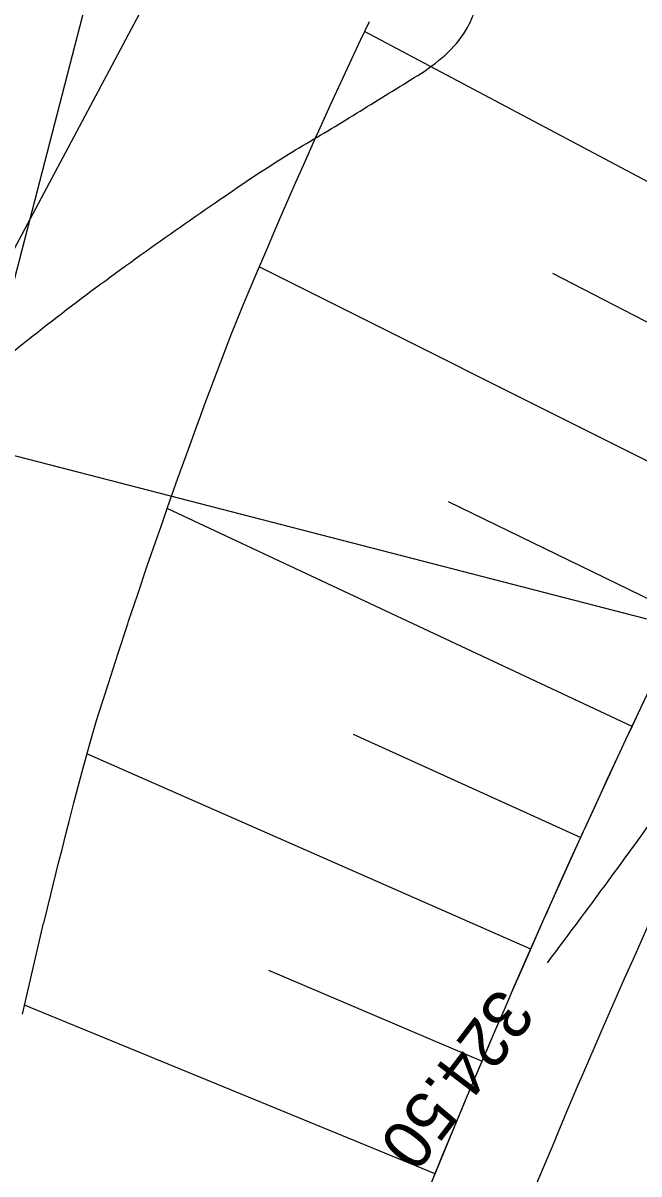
# Model space of a CAD drawing. Extents: x -564043 to -563833, y -1163561 to -1163412.
# Drawn here: x -563977.47 to -563971.17, y -1163485.61 to -1163473.83 of the extents above; entities that cross this region are included whole.
import ezdxf

# ---------------------------------------------------------------- set-up
doc = ezdxf.new("R2010")
doc.units = 0
for name, color, linetype in [('5', 7, 'Continuous'), ('_popis staničení T1', 7, 'Continuous'), ('Definiční bod kú', 7, 'Continuous'), ('Line', 7, 'Continuous'), ('Vrstva 24', 7, 'Continuous'), ('Vrstva 25', 7, 'Continuous'), ('Vrstva 26', 7, 'Continuous')]:
    doc.layers.add(name, color=color, linetype=linetype)

msp = doc.modelspace()

# ---------------------------------------------------------------- linework, layer by layer
for points in [[(-563973.328, -1163485.785), (-563972.941, -1163484.852), (-563972.655, -1163484.178), (-563972.545, -1163483.923), (-563972.444, -1163483.689), (-563972.14, -1163482.998), (-563971.736, -1163482.1), (-563971.725, -1163482.077), (-563971.302, -1163481.16), (-563970.869, -1163480.247), (-563970.771, -1163480.044), (-563970.427, -1163479.339), (-563969.976, -1163478.435), (-563969.759, -1163478.009), (-563969.516, -1163477.536), (-563969.047, -1163476.642), (-563968.703, -1163475.998), (-563968.571, -1163475.754), (-563968.096, -1163474.874), (-563967.621, -1163473.994), (-563967.145, -1163473.115)], [(-563977.473, -1163483.969), (-563977.402, -1163483.659), (-563977.329, -1163483.35), (-563977.256, -1163483.041), (-563977.255, -1163483.039), (-563977.18, -1163482.732), (-563977.103, -1163482.424), (-563977.068, -1163482.285), (-563977.025, -1163482.116), (-563976.995, -1163482), (-563976.946, -1163481.808), (-563976.865, -1163481.5), (-563976.782, -1163481.193), (-563976.715, -1163480.966), (-563976.691, -1163480.89), (-563976.594, -1163480.588), (-563976.497, -1163480.287), (-563976.398, -1163479.986), (-563976.395, -1163479.977), (-563976.387, -1163479.951), (-563976.298, -1163479.685), (-563976.196, -1163479.385), (-563976.093, -1163479.085), (-563976.042, -1163478.94), (-563975.988, -1163478.786), (-563975.883, -1163478.488), (-563975.775, -1163478.189), (-563975.682, -1163477.935), (-563975.667, -1163477.891), (-563975.6, -1163477.71), (-563975.556, -1163477.594), (-563975.445, -1163477.297), (-563975.332, -1163477.001), (-563975.305, -1163476.935), (-563975.211, -1163476.708), (-563975.089, -1163476.416), (-563974.965, -1163476.124), (-563974.891, -1163475.952), (-563974.84, -1163475.833), (-563974.714, -1163475.543), (-563974.69, -1163475.488), (-563974.586, -1163475.253), (-563974.462, -1163474.975), (-563974.457, -1163474.964), (-563974.326, -1163474.675), (-563974.194, -1163474.388), (-563974.06, -1163474.1), (-563974.016, -1163474.005), (-563973.925, -1163473.814)], [(-563977.473, -1163483.969), (-563977.402, -1163483.659), (-563977.329, -1163483.35), (-563977.256, -1163483.041), (-563977.255, -1163483.039), (-563977.18, -1163482.732), (-563977.103, -1163482.424), (-563977.068, -1163482.285), (-563977.025, -1163482.116), (-563976.995, -1163482), (-563976.946, -1163481.808), (-563976.865, -1163481.5), (-563976.782, -1163481.193), (-563976.715, -1163480.966), (-563976.691, -1163480.89), (-563976.594, -1163480.588), (-563976.497, -1163480.287), (-563976.398, -1163479.986), (-563976.395, -1163479.977), (-563976.387, -1163479.951), (-563976.298, -1163479.685), (-563976.196, -1163479.385), (-563976.093, -1163479.085), (-563976.042, -1163478.94), (-563975.988, -1163478.786), (-563975.883, -1163478.488), (-563975.775, -1163478.189), (-563975.682, -1163477.935), (-563975.667, -1163477.891), (-563975.6, -1163477.71), (-563975.556, -1163477.594), (-563975.445, -1163477.297), (-563975.332, -1163477.001), (-563975.305, -1163476.935), (-563975.211, -1163476.708), (-563975.089, -1163476.416), (-563974.965, -1163476.124), (-563974.891, -1163475.952), (-563974.84, -1163475.833), (-563974.714, -1163475.543), (-563974.69, -1163475.488), (-563974.586, -1163475.253), (-563974.462, -1163474.975), (-563974.457, -1163474.964), (-563974.326, -1163474.675), (-563974.194, -1163474.388), (-563974.06, -1163474.1), (-563974.016, -1163474.005), (-563973.925, -1163473.814)], [(-563973.287, -1163485.685), (-563973.173, -1163485.407), (-563973.058, -1163485.13), (-563972.942, -1163484.854), (-563972.941, -1163484.852), (-563972.826, -1163484.578), (-563972.708, -1163484.302), (-563972.655, -1163484.178), (-563972.59, -1163484.027), (-563972.545, -1163483.923), (-563972.471, -1163483.751), (-563972.351, -1163483.477), (-563972.23, -1163483.202), (-563972.14, -1163482.998), (-563972.109, -1163482.928), (-563971.987, -1163482.654), (-563971.864, -1163482.381), (-563971.74, -1163482.108), (-563971.736, -1163482.1), (-563971.725, -1163482.077), (-563971.615, -1163481.836), (-563971.49, -1163481.563), (-563971.363, -1163481.292), (-563971.302, -1163481.16), (-563971.236, -1163481.02), (-563971.108, -1163480.749)], [(-563972.249, -1163485.789), (-563972.135, -1163485.515), (-563972.02, -1163485.241), (-563972.019, -1163485.239), (-563971.905, -1163484.968), (-563971.789, -1163484.695), (-563971.736, -1163484.572), (-563971.672, -1163484.422), (-563971.627, -1163484.32), (-563971.554, -1163484.15), (-563971.435, -1163483.878), (-563971.316, -1163483.606), (-563971.226, -1163483.404), (-563971.195, -1163483.335), (-563971.074, -1163483.064)]]:
    msp.add_lwpolyline(points)
at = {"layer": '5'}
msp.add_line((-563977.993, -1163478.142), (-563940.586, -1163487.812), dxfattribs=at)
at = {"layer": '_popis staničení T1'}
msp.add_lwpolyline([(-563977.993, -1163478.142), (-563974.239, -1163463.619)], dxfattribs=at)
at = {"layer": 'Definiční bod kú'}
msp.add_lwpolyline([(-564014.48, -1163510.5), (-564004.65, -1163507.04), (-563996.46, -1163502.51), (-563993.72, -1163500.97), (-563990.58, -1163498.69), (-563987.18, -1163495.32), (-563983.19, -1163487.81), (-563979.82, -1163480.39), (-563975.55, -1163472.37), (-563971.76, -1163466.68), (-563970.57, -1163458.32), (-563969.42, -1163449.87), (-563967.93, -1163441.99), (-563966.12, -1163434.66), (-563963.95, -1163427.04), (-563963.19, -1163422.98), (-563961.48, -1163418.93), (-563957.126, -1163412.494)], dxfattribs=at)
at = {"layer": 'Line'}
for p, q in [((-563969.002, -1163476.558), (-563973.975, -1163473.918)), ((-563970.148, -1163478.78), (-563975.051, -1163476.325)), ((-563972.054, -1163476.391), (-563969.582, -1163477.666)), ((-563973.121, -1163478.726), (-563970.702, -1163479.901)), ((-563971.24, -1163481.029), (-563975.992, -1163478.796)), ((-563974.092, -1163481.106), (-563971.765, -1163482.164)), ((-563972.275, -1163483.305), (-563976.813, -1163481.308)), ((-563974.958, -1163483.521), (-563972.771, -1163484.452)), ((-563973.253, -1163485.605), (-563977.452, -1163483.877))]:
    msp.add_line(p, q, dxfattribs=at)
at = {"layer": 'Vrstva 24'}
for points in [[(-563978.854, -1163478.318), (-563978.568, -1163478.038), (-563977.805, -1163477.383), (-563977.021, -1163476.763), (-563975.398, -1163475.598), (-563974.826, -1163475.219), (-563974.239, -1163474.866), (-563973.653, -1163474.504), (-563973.089, -1163474.098), (-563972.904, -1163473.842), (-563972.822, -1163473.635), (-563972.621, -1163472.787), (-563972.462, -1163471.939), (-563972.345, -1163470.233), (-563972.381, -1163469.548), (-563972.436, -1163468.863), (-563972.493, -1163468.177), (-563972.536, -1163467.491), (-563972.544, -1163467.019), (-563972.616, -1163466.703), (-563972.792, -1163466.372), (-563972.978, -1163466.055), (-563973.374, -1163465.439), (-563974.845, -1163463.261), (-563976.988, -1163460.027), (-563977.624, -1163458.769), (-563978.204, -1163457.386), (-563978.773, -1163456.191), (-563980.32, -1163452.694), (-563980.848, -1163451.287), (-563981.348, -1163449.871), (-563981.843, -1163448.453), (-563982.355, -1163447.041), (-563982.812, -1163445.847), (-563984.84, -1163441.02)], [(-563987.107, -1163486.915), (-563987.454, -1163489.613), (-563987.517, -1163490.15), (-563987.54, -1163490.422), (-563987.53, -1163490.559), (-563987.493, -1163490.695), (-563987.417, -1163490.784), (-563987.298, -1163490.832), (-563987.065, -1163490.801), (-563986.897, -1163490.636), (-563986.866, -1163490.616), (-563986.653, -1163490.561), (-563986.65, -1163490.24), (-563986.645, -1163490.2), (-563986.382, -1163489.381), (-563986.092, -1163488.576), (-563985.799, -1163487.775), (-563985.528, -1163486.967), (-563985.38, -1163486.476), (-563984.961, -1163484.997), (-563984.678, -1163484.011), (-563984.372, -1163483.032), (-563984.225, -1163482.649), (-563983.962, -1163482.075), (-563983.672, -1163481.512), (-563983.189, -1163480.348), (-563983.119, -1163479.959), (-563982.881, -1163478.598), (-563982.738, -1163477.921), (-563982.65, -1163477.583), (-563982.6, -1163477.415), (-563982.546, -1163477.247), (-563982.332, -1163477.109), (-563982.215, -1163477.074), (-563982.092, -1163477.059), (-563981.971, -1163477.035), (-563981.858, -1163476.974), (-563981.222, -1163476.317), (-563980.763, -1163475.576), (-563980.303, -1163473.933), (-563980.283, -1163473.505), (-563980.299, -1163473.076), (-563980.318, -1163472.648), (-563980.308, -1163472.221), (-563980.208, -1163471.241), (-563979.978, -1163470.27), (-563979.506, -1163469.655), (-563979.053, -1163469.383), (-563978.331, -1163469.068), (-563977.756, -1163469.029), (-563977.053, -1163469.053), (-563976.495, -1163468.977), (-563976.227, -1163468.861), (-563976.095, -1163468.775), (-563975.963, -1163468.666), (-563975.645, -1163468.239), (-563975.569, -1163468.015), (-563975.54, -1163467.788), (-563975.712, -1163467.263), (-563975.92, -1163467.014), (-563976.134, -1163466.799), (-563976.603, -1163466.431), (-563977.767, -1163465.694), (-563978.114, -1163465.416), (-563978.319, -1163465.046), (-563978.354, -1163464.593), (-563978.366, -1163464.139), (-563978.374, -1163463.685), (-563978.396, -1163463.232), (-563978.403, -1163463.165), (-563978.508, -1163462.771), (-563978.665, -1163462.394), (-563979.088, -1163461.691), (-563979.473, -1163461.171), (-563980.119, -1163460.346)], [(-563978.297, -1163509.021), (-563978.261, -1163509.003), (-563973.613, -1163506.565), (-563973.263, -1163506.351), (-563972.852, -1163506.074), (-563964.784, -1163500.778), (-563963.064, -1163499.262), (-563960.133, -1163495.845), (-563958.857, -1163494.133), (-563956.661, -1163490.461), (-563954.703, -1163486.917), (-563951.017, -1163480.396), (-563950.659, -1163479.782), (-563950.563, -1163479.619)]]:
    msp.add_spline(points, degree=3, dxfattribs=at)
at = {"layer": 'Vrstva 25'}
msp.add_spline([(-563979.181, -1163499.008), (-563978.428, -1163498.506), (-563977.533, -1163497.79), (-563971.745, -1163492.882), (-563969.933, -1163491.157), (-563968.824, -1163489.747), (-563966.163, -1163485.494), (-563965.399, -1163484.181), (-563964.1, -1163481.868), (-563961.431, -1163477.021), (-563960.731, -1163475.725), (-563960.044, -1163474.189), (-563959.617, -1163472.641), (-563959.116, -1163469.866), (-563959.228, -1163469.046), (-563959.512, -1163468.326), (-563959.82, -1163467.638), (-563960.515, -1163466.313), (-563961.208, -1163465.1)], degree=3, dxfattribs=at)
at = {"layer": 'Vrstva 26'}
for points in [[(-563972.104, -1163483.444), (-563971.432, -1163482.54), (-563969.672, -1163480.022), (-563968.003, -1163477.443), (-563966.946, -1163475.644), (-563966.582, -1163474.952), (-563966.094, -1163473.851), (-563965.88, -1163473.286), (-563965.678, -1163472.709), (-563965.489, -1163472.088), (-563965.344, -1163471.461), (-563965.237, -1163470.83), (-563965.169, -1163470.196), (-563965.25, -1163468.999), (-563965.418, -1163468.435), (-563965.618, -1163467.888), (-563966.136, -1163466.849), (-563967.179, -1163465.223), (-563969.294, -1163462.205), (-563970.81, -1163460.003), (-563971.343, -1163459.213), (-563971.719, -1163458.626), (-563972.18, -1163457.904), (-563973.29, -1163456.114), (-563973.826, -1163455.207), (-563974.35, -1163454.292), (-563975.821, -1163451.273), (-563976.512, -1163449.594), (-563977.063, -1163448.162), (-563977.464, -1163447.121)], [(-563980.746, -1163506.255), (-563980.047, -1163505.928), (-563978.898, -1163505.186), (-563978.091, -1163504.559), (-563977.304, -1163503.908), (-563976.514, -1163503.264), (-563975.695, -1163502.656), (-563974.591, -1163501.929), (-563973.468, -1163501.232), (-563972.341, -1163500.538), (-563971.226, -1163499.825), (-563970.447, -1163499.268), (-563969.15, -1163497.951), (-563964.517, -1163492.611), (-563963.2, -1163490.7), (-563960.284, -1163485.41), (-563958.779, -1163482.786), (-563956.142, -1163478.307), (-563954.428, -1163475.228)]]:
    msp.add_spline(points, degree=3, dxfattribs=at)

# ---------------------------------------------------------------- texts
at = {"layer": 'Vrstva 25'}
msp.add_text('324.50', height=0.5, rotation=232.6996, dxfattribs=at).set_placement((-563972.605, -1163483.676))

doc.saveas('drawing.dxf')
